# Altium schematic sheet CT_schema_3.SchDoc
size 294 x 134 mm
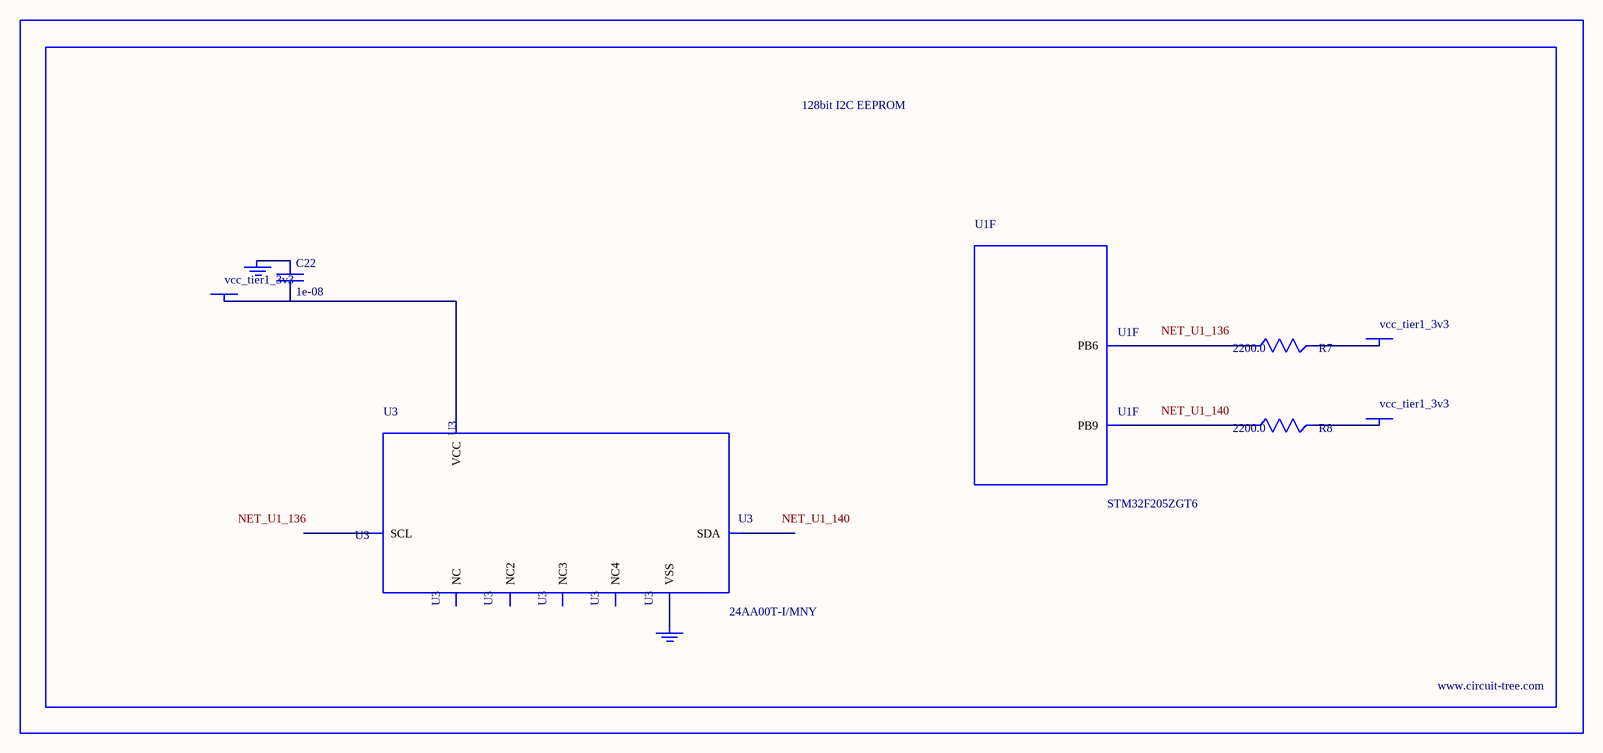
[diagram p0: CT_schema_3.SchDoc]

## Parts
BORDER2  (no value)
C22  1e-08  [C0402]
GND_INSTANCE_2_0  (no value)
GND_INSTANCE_2_1  (no value)
POWER_INSTANCE_2_0  vcc_tier1_3v3
POWER_INSTANCE_2_1  vcc_tier1_3v3
POWER_INSTANCE_2_2  vcc_tier1_3v3
R7  2200.0  [R0603]
R8  2200.0  [R0603]
U1  STM32F205ZGT6  [LQFP144]  (part F of 12)
U3  24AA00T-I/MNY  [TDFN-8/6MM]

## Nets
NetC22_1: C22.1 GND_INSTANCE_2_0.0(GND)
NetC22_2: C22.2 POWER_INSTANCE_2_0.0(PWR) U3.8(VCC)
NetGND_INSTANCE_2_1_0: GND_INSTANCE_2_1.0(GND) U3.4(VSS)
NetPOWER_INSTANCE_2_1_0: POWER_INSTANCE_2_1.0(PWR) R7.2
NetPOWER_INSTANCE_2_2_0: POWER_INSTANCE_2_2.0(PWR) R8.2
NetR7_1: R7.1 U1.136(PB6)
NetR8_1: R8.1 U1.140(PB9)

Not connected (* = marked no-connect by the designer): U3 1(NC) 2(NC2) 3(NC3) 5(SDA) 6(SCL) 7(NC4)

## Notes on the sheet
- Labels drawn without touching a wire or pin: NET_U1_136, NET_U1_140

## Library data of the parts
BORDER2 = BORDER_PAGE2
C22 = C0402C103K3RAC
GND_INSTANCE_2_0 GND_INSTANCE_2_1 = GND
POWER_INSTANCE_2_0-POWER_INSTANCE_2_2 = PWR
R7 R8 = RC0603JR-072K2L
